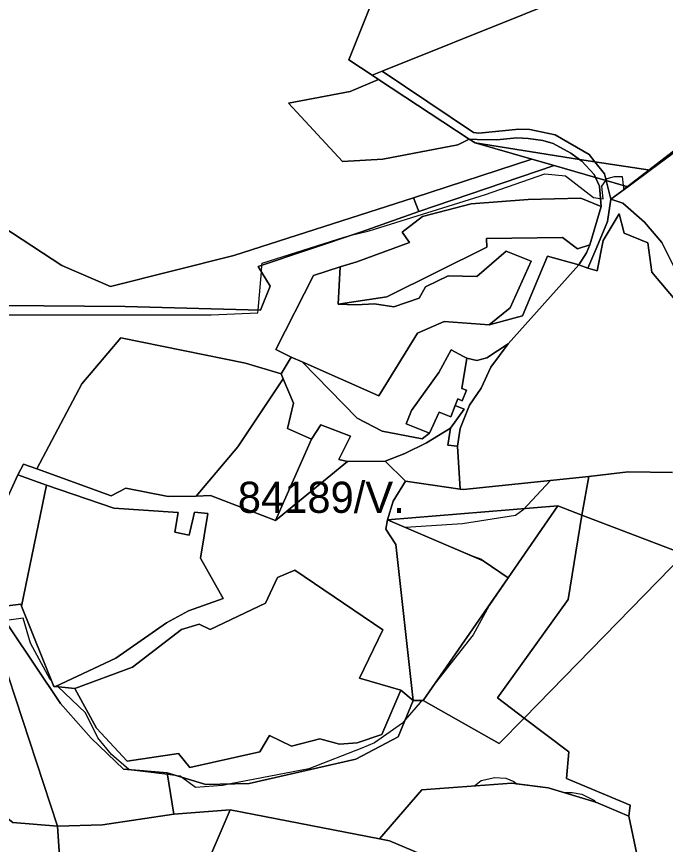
# Model space of a CAD drawing. Extents: x -477304 to -465429, y -1159113 to -1149210.
# Drawn here: x -475844.7 to -475532.4, y -1153787.9 to -1153389.4 of the extents above; entities that cross this region are included whole.
import ezdxf

# ---------------------------------------------------------------- set-up
doc = ezdxf.new("R2010")
doc.units = 0
for name, color, linetype in [('BPEJ_s', 7, 'Continuous'), ('ostatni_s', 7, 'Continuous'), ('PUPFL_s', 7, 'Continuous'), ('trav_porost_s', 7, 'Continuous'), ('zahrada_s', 7, 'Continuous')]:
    doc.layers.add(name, color=color, linetype=linetype)

msp = doc.modelspace()

# ---------------------------------------------------------------- linework, layer by layer
at = {"layer": 'BPEJ_s'}
for points in [[(-475851.96, -1153533), (-475751, -1153533), (-475728.5, -1153532), (-475728.39, -1153530.71), (-475726.86, -1153512.29), (-475726.59, -1153509.11), (-475726.5, -1153508), (-475687, -1153495.5), (-475683.62, -1153494.65), (-475675, -1153492.5), (-475619, -1153475), (-475590.5, -1153465), (-475580.5, -1153466), (-475567, -1153476.5), (-475563.7, -1153476.91), (-475562.34, -1153477.08), (-475562.99, -1153470.93), (-475561.09, -1153468.27), (-475560.98, -1153468.11), (-475560.95, -1153468.06), (-475560.44, -1153467.35), (-475556.88, -1153466.33), (-475553.31, -1153466.33), (-475552.77, -1153470.67), (-475552.67, -1153471.46), (-475552.54, -1153472.53), (-475550.84, -1153471.23), (-475540.39, -1153463.19), (-475520, -1153447.5)], [(-475851.96, -1153533), (-475751, -1153533), (-475728.5, -1153532), (-475728.39, -1153530.71), (-475726.86, -1153512.29), (-475726.59, -1153509.11), (-475726.5, -1153508), (-475687, -1153495.5), (-475683.62, -1153494.65), (-475675, -1153492.5), (-475619, -1153475), (-475590.5, -1153465), (-475580.5, -1153466), (-475567, -1153476.5), (-475563.7, -1153476.91), (-475562.34, -1153477.08), (-475562.99, -1153470.93), (-475561.09, -1153468.27), (-475560.98, -1153468.11), (-475560.95, -1153468.06), (-475560.44, -1153467.35), (-475556.88, -1153466.33), (-475553.31, -1153466.33), (-475552.77, -1153470.67), (-475552.67, -1153471.46), (-475552.54, -1153472.53), (-475550.84, -1153471.23), (-475540.39, -1153463.19), (-475520, -1153447.5)], [(-475528.97, -1153608.89), (-475550.34, -1153608.5), (-475569.29, -1153610.8), (-475587.68, -1153612.72), (-475601, -1153627), (-475604.5, -1153629.5), (-475630, -1153633.5), (-475657.46, -1153635.27), (-475625.43, -1153649.02), (-475621, -1153650.5), (-475619.57, -1153651.67), (-475608.06, -1153659.56), (-475617.27, -1153672.83), (-475625, -1153687), (-475643.27, -1153710.28), (-475649.02, -1153718.57), (-475649.77, -1153718.57), (-475650.5, -1153719.5), (-475657.63, -1153727.89), (-475659, -1153729.5), (-475672.5, -1153739), (-475678.5, -1153741.5), (-475704, -1153751.5), (-475741.66, -1153758.76), (-475745.5, -1153759.5), (-475758.5, -1153760.5), (-475765.25, -1153755.55), (-475766, -1153755), (-475767.8, -1153754.78), (-475768.33, -1153754.71), (-475772.1, -1153754.25), (-475790.5, -1153752), (-475790.7, -1153751.82), (-475799, -1153744.5), (-475805.5, -1153736.5), (-475811.5, -1153724.5), (-475824.88, -1153711.9)], [(-475528.97, -1153608.89), (-475550.34, -1153608.5), (-475569.29, -1153610.8), (-475587.68, -1153612.72), (-475601, -1153627), (-475604.5, -1153629.5), (-475630, -1153633.5), (-475657.46, -1153635.27), (-475625.43, -1153649.02), (-475621, -1153650.5), (-475619.57, -1153651.67), (-475608.06, -1153659.56), (-475617.27, -1153672.83), (-475625, -1153687), (-475643.27, -1153710.28), (-475649.02, -1153718.57), (-475649.77, -1153718.57), (-475650.5, -1153719.5), (-475657.63, -1153727.89), (-475659, -1153729.5), (-475672.5, -1153739), (-475678.5, -1153741.5), (-475704, -1153751.5), (-475741.66, -1153758.76), (-475745.5, -1153759.5), (-475758.5, -1153760.5), (-475765.25, -1153755.55), (-475766, -1153755), (-475767.8, -1153754.78), (-475768.33, -1153754.71), (-475772.1, -1153754.25), (-475790.5, -1153752), (-475790.7, -1153751.82)], [(-475790.7, -1153751.82), (-475799, -1153744.5), (-475805.5, -1153736.5), (-475811.5, -1153724.5), (-475824.88, -1153711.9), (-475825.99, -1153711.78), (-475826.72, -1153711.78), (-475827.76, -1153709.2), (-475828.5, -1153708.5), (-475838, -1153691), (-475841.5, -1153679), (-475849.5, -1153680)], [(-475824.88, -1153711.9), (-475825.99, -1153711.78), (-475826.72, -1153711.78), (-475827.76, -1153709.2), (-475828.5, -1153708.5), (-475838, -1153691), (-475841.5, -1153679), (-475849.5, -1153680)], [(-475756.99, -1153806.33), (-475741.9, -1153771.2), (-475670.03, -1153785.19), (-475649.72, -1153761.59), (-475624.25, -1153759.73), (-475621.1, -1153757.1), (-475614.5, -1153755.6), (-475609.2, -1153756), (-475605.3, -1153757.5), (-475604.03, -1153758.71), (-475588.9, -1153760.6), (-475581.23, -1153762.93), (-475577.3, -1153762.9), (-475572.6, -1153763.7), (-475566.5, -1153766.7), (-475566.24, -1153767.48), (-475565.95, -1153767.57), (-475550.09, -1153774.28), (-475542.44, -1153810.09)], [(-475624.25, -1153759.73), (-475621.1, -1153757.1), (-475614.5, -1153755.6), (-475609.2, -1153756), (-475605.3, -1153757.5), (-475604.03, -1153758.71), (-475588.9, -1153760.6), (-475581.23, -1153762.93), (-475577.3, -1153762.9), (-475572.6, -1153763.7), (-475566.5, -1153766.7), (-475566.24, -1153767.48), (-475565.95, -1153767.57), (-475550.09, -1153774.28), (-475542.44, -1153810.09)], [(-475756.99, -1153806.33), (-475741.9, -1153771.2), (-475670.03, -1153785.19), (-475649.72, -1153761.59), (-475624.25, -1153759.73)]]:
    msp.add_lwpolyline(points, dxfattribs=at)
at = {"layer": 'ostatni_s'}
for points in [[(-475668.69, -1153415.63), (-475624.85, -1153445.17), (-475622.17, -1153445.5), (-475602.95, -1153443.6), (-475597.74, -1153443.76), (-475585.5, -1153446.34), (-475569.09, -1153455.81), (-475566.37, -1153459.27), (-475573.81, -1153458.15), (-475577.89, -1153455.17), (-475586.46, -1153450.46), (-475591.43, -1153449.06), (-475598.48, -1153448), (-475603.99, -1153447.8), (-475613.57, -1153448.64), (-475622.99, -1153448.58), (-475626.84, -1153448.33), (-475670.42, -1153419.59), (-475673.48, -1153417.57)], [(-475572.58, -1153459.04), (-475573.81, -1153458.15), (-475566.37, -1153459.27), (-475561.78, -1153465.12), (-475560.87, -1153468.33), (-475566.07, -1153466.83), (-475566.74, -1153465.34)], [(-475569.79, -1153510.4), (-475574.16, -1153508.94), (-475570.35, -1153503.17), (-475568.84, -1153499.25), (-475563.38, -1153480.81), (-475564.19, -1153471), (-475566.07, -1153466.83), (-475560.87, -1153468.33), (-475558.66, -1153477.28), (-475560.35, -1153488.09), (-475565.42, -1153500.31)], [(-475574.73, -1153501.1), (-475581.96, -1153495.66), (-475618.59, -1153496.19), (-475618.43, -1153500.42), (-475666.5, -1153524.3), (-475689.92, -1153527.88), (-475688.9, -1153509.91), (-475680.91, -1153507.43), (-475655.59, -1153498.07), (-475659.07, -1153493.19), (-475649.4, -1153485.57), (-475625.88, -1153479.58), (-475598.55, -1153477.36), (-475573.19, -1153476.72), (-475563.38, -1153480.81), (-475568.84, -1153499.25)], [(-475628.05, -1153553.86), (-475623.13, -1153554.87), (-475618.43, -1153553.69), (-475608.08, -1153546.94), (-475616.41, -1153558.15), (-475621.09, -1153568.23), (-475626.74, -1153576.47), (-475631.2, -1153587.68), (-475632.49, -1153596.14), (-475637.19, -1153595.7), (-475635.79, -1153587.57), (-475629.29, -1153578.27), (-475633.55, -1153576.51), (-475632.34, -1153573.45), (-475630.17, -1153574.31), (-475628.17, -1153569.26), (-475630.34, -1153568.4)], [(-475641.43, -1153560.73), (-475635.51, -1153549.81), (-475629.63, -1153553), (-475628.05, -1153553.86), (-475630.34, -1153568.4), (-475628.17, -1153569.26), (-475630.17, -1153574.31), (-475632.34, -1153573.45), (-475633.55, -1153576.51), (-475635.72, -1153581.96), (-475641.34, -1153579.73), (-475645.88, -1153589.88), (-475657.19, -1153585.39), (-475654.62, -1153578.92)]]:
    msp.add_lwpolyline(points, close=True, dxfattribs=at)
at = {"layer": 'PUPFL_s'}
for points in [[(-475515.92, -1153287.9), (-475519.18, -1153298.61), (-475523.09, -1153304.39), (-475528.76, -1153312.77), (-475531.14, -1153360.32), (-475668.69, -1153415.63), (-475673.48, -1153417.57), (-475684.71, -1153410.17), (-475659.25, -1153346.36), (-475665.79, -1153319.52), (-475674.43, -1153216.71), (-475653.9, -1153209.59), (-475627.89, -1153203.74), (-475613.03, -1153201.52), (-475601.83, -1153200.23), (-475576.05, -1153197.07), (-475570.45, -1153196.51), (-475559.97, -1153201.88), (-475555.37, -1153214), (-475529.09, -1153283.3), (-475526.18, -1153282.23), (-475523.2, -1153281.06), (-475517.18, -1153278.69), (-475515.51, -1153278.03)], [(-475597.74, -1153443.76), (-475602.95, -1153443.6), (-475622.17, -1153445.5), (-475624.85, -1153445.17), (-475668.69, -1153415.63), (-475531.14, -1153360.32), (-475531.2, -1153370.12), (-475526.66, -1153384.3), (-475514.69, -1153395.34), (-475500.44, -1153434.27), (-475539.7, -1153463.29), (-475566.37, -1153459.27), (-475569.09, -1153455.81), (-475585.5, -1153446.34)], [(-475668.41, -1153458.08), (-475687.79, -1153459.15), (-475713.78, -1153431.01), (-475684.2, -1153425.47), (-475670.42, -1153419.59), (-475626.84, -1153448.33), (-475632.36, -1153451.19)], [(-475493.46, -1153459.75), (-475492.82, -1153484.93), (-475485.96, -1153525.23), (-475485.53, -1153549.13), (-475484.58, -1153602.24), (-475503.68, -1153602.19), (-475500.98, -1153601.49), (-475497.4, -1153591.91), (-475497, -1153568.53), (-475498.83, -1153560.34), (-475509.21, -1153546.37), (-475515.54, -1153541.79), (-475521.85, -1153525.95), (-475527.95, -1153510.61), (-475534.2, -1153498.06), (-475542.48, -1153488.38), (-475552.87, -1153479.13), (-475558.66, -1153477.28), (-475550.55, -1153471.31), (-475539.7, -1153463.29), (-475500.44, -1153434.27)], [(-475598.48, -1153448), (-475591.43, -1153449.06), (-475586.46, -1153450.46), (-475577.89, -1153455.17), (-475573.81, -1153458.15), (-475623.93, -1153450.13), (-475626.84, -1153448.33), (-475622.99, -1153448.58), (-475613.57, -1153448.64), (-475603.99, -1153447.8)], [(-475596.78, -1153457.97), (-475623.93, -1153450.13), (-475573.81, -1153458.15), (-475572.58, -1153459.04), (-475566.74, -1153465.34), (-475566.07, -1153466.83), (-475585.93, -1153461.1)], [(-475585.93, -1153461.1), (-475651.06, -1153483.16), (-475653.63, -1153476.63), (-475596.78, -1153457.97)], [(-475561.78, -1153465.12), (-475566.37, -1153459.27), (-475539.7, -1153463.29), (-475550.55, -1153471.31), (-475560.87, -1153468.33)], [(-475560.87, -1153468.33), (-475550.55, -1153471.31), (-475558.66, -1153477.28)], [(-475860.13, -1153579.58), (-475872.32, -1153636.78), (-475862.21, -1153666.07), (-475825.03, -1153779.08), (-475846.52, -1153777.32), (-475860.49, -1153766.45), (-475869.26, -1153745.4), (-475879, -1153647.09), (-475892.72, -1153543.15), (-475897.34, -1153514.33), (-475910.3, -1153503.15), (-475912.4, -1153498.87), (-475875.17, -1153475.08), (-475874.89, -1153478.85), (-475851.17, -1153528.5)], [(-475799.43, -1153519.25), (-475740.15, -1153504.46), (-475653.63, -1153476.63), (-475651.06, -1153483.16), (-475678.61, -1153492.97), (-475728.44, -1153509.73), (-475722.59, -1153519.2), (-475727.29, -1153530.74), (-475792.49, -1153528.95), (-475851.17, -1153528.5), (-475874.89, -1153478.85), (-475875.17, -1153475.08), (-475822.83, -1153509.17)], [(-475540.89, -1153498.35), (-475552.3, -1153493.56), (-475554.75, -1153484.27), (-475562.32, -1153497.18), (-475565.19, -1153511.69), (-475569.79, -1153510.4), (-475565.42, -1153500.31), (-475560.35, -1153488.09), (-475558.66, -1153477.28), (-475552.87, -1153479.13), (-475542.48, -1153488.38), (-475534.2, -1153498.06), (-475527.95, -1153510.61), (-475521.85, -1153525.95), (-475527.66, -1153525.75), (-475539.01, -1153512.42)], [(-475636.97, -1153514.1), (-475647.89, -1153519.53), (-475650.98, -1153524.94), (-475663.06, -1153529.12), (-475672.45, -1153527.72), (-475681.19, -1153528.16), (-475689.92, -1153527.88), (-475666.5, -1153524.3), (-475618.43, -1153500.42), (-475618.59, -1153496.19), (-475581.96, -1153495.66), (-475574.73, -1153501.1), (-475568.84, -1153499.25), (-475570.35, -1153503.17), (-475574.16, -1153508.94), (-475589.14, -1153504.68), (-475601.27, -1153533.38), (-475617.29, -1153537.75), (-475607.21, -1153529.51), (-475597.04, -1153507.15), (-475608.99, -1153502.36), (-475623.17, -1153514.55)], [(-475858.69, -1153641.76), (-475844.11, -1153609.9), (-475830.23, -1153614.94), (-475842.24, -1153673.19), (-475842.66, -1153672.16), (-475850.33, -1153673.17), (-475854.01, -1153645.2)], [(-475631.23, -1153616.85), (-475629.52, -1153617.08), (-475569.29, -1153610.8), (-475572.66, -1153629.41), (-475584.12, -1153624.95), (-475666.11, -1153631.56), (-475663.45, -1153622.65), (-475657.44, -1153613.04)], [(-475608.06, -1153659.56), (-475620.08, -1153651.32), (-475666.11, -1153631.56), (-475584.12, -1153624.95)], [(-475612.42, -1153739.33), (-475649.02, -1153718.57), (-475608.06, -1153659.56), (-475584.12, -1153624.95), (-475572.66, -1153629.41), (-475579.17, -1153669.95), (-475613.16, -1153717.34), (-475600.39, -1153727.01)], [(-475523.34, -1153648.1), (-475600.39, -1153727.01), (-475613.16, -1153717.34), (-475579.17, -1153669.95), (-475572.66, -1153629.41)], [(-475772.23, -1153753.44), (-475769.04, -1153773.27), (-475803.37, -1153778.4), (-475825.03, -1153779.08), (-475862.21, -1153666.07), (-475860.03, -1153665.68), (-475823.48, -1153720.08), (-475808.77, -1153736.65), (-475793.21, -1153751.6)], [(-475580.1, -1153756.17), (-475549.39, -1153768.9), (-475550.09, -1153774.28), (-475565.95, -1153767.57), (-475588.9, -1153760.6), (-475606.35, -1153758.42), (-475649.72, -1153761.59), (-475670.03, -1153785.19), (-475741.9, -1153771.2), (-475769.04, -1153773.27), (-475772.23, -1153753.44), (-475753.57, -1153759.08), (-475732.71, -1153758.52), (-475681.47, -1153746.89), (-475660.99, -1153736), (-475653.76, -1153718.54), (-475649.02, -1153718.57), (-475612.42, -1153739.33), (-475600.39, -1153727.01), (-475578.88, -1153743.31)]]:
    msp.add_lwpolyline(points, close=True, dxfattribs=at)
for points in [[(-475659.25, -1153346.36), (-475684.71, -1153410.17), (-475673.48, -1153417.57), (-475670.42, -1153419.59), (-475684.2, -1153425.47), (-475713.78, -1153431.01), (-475687.79, -1153459.15), (-475668.41, -1153458.08), (-475632.36, -1153451.19), (-475626.84, -1153448.33), (-475623.93, -1153450.13), (-475596.78, -1153457.97), (-475653.63, -1153476.63), (-475740.15, -1153504.46), (-475799.43, -1153519.25), (-475822.83, -1153509.17), (-475875.17, -1153475.08), (-475877.59, -1153433.1), (-475882.33, -1153398.08), (-475880.77, -1153394.71), (-475851.63, -1153345.16)], [(-475851.17, -1153528.5), (-475792.49, -1153528.95), (-475727.29, -1153530.74), (-475722.59, -1153519.2), (-475728.44, -1153509.73), (-475678.61, -1153492.97), (-475651.06, -1153483.16), (-475585.93, -1153461.1), (-475566.07, -1153466.83), (-475564.19, -1153471), (-475563.38, -1153480.81), (-475573.19, -1153476.72), (-475598.55, -1153477.36), (-475625.88, -1153479.58), (-475649.4, -1153485.57), (-475659.07, -1153493.19), (-475655.59, -1153498.07), (-475680.91, -1153507.43), (-475688.9, -1153509.91), (-475701.83, -1153513.93), (-475719.84, -1153549.68), (-475712.45, -1153553.33), (-475717.35, -1153561.4), (-475734.49, -1153556.24), (-475794.54, -1153544.05), (-475813.32, -1153566.21), (-475834.96, -1153607.13), (-475841.29, -1153604.8), (-475844.11, -1153609.9), (-475858.69, -1153641.76)], [(-476034.71, -1153609.09), (-475997.76, -1153576.14), (-475991.17, -1153546.59), (-475941.59, -1153528.51), (-475897.34, -1153514.33), (-475892.72, -1153543.15), (-475879, -1153647.09), (-475869.26, -1153745.4), (-475860.49, -1153766.45), (-475846.52, -1153777.32), (-475825.03, -1153779.08), (-475814.63, -1153935.2), (-475814.03, -1153985.87), (-475825.65, -1154044.41)], [(-475456.54, -1153880.98), (-475541.07, -1153838.67), (-475542.44, -1153810.09), (-475550.09, -1153774.28), (-475549.39, -1153768.9), (-475580.1, -1153756.17), (-475578.88, -1153743.31), (-475600.39, -1153727.01), (-475523.34, -1153648.1), (-475572.66, -1153629.41), (-475569.29, -1153610.8), (-475550.34, -1153608.5), (-475528.97, -1153608.89)], [(-475850.33, -1153673.17), (-475842.66, -1153672.16), (-475842.24, -1153673.19), (-475826.72, -1153711.78), (-475825.99, -1153711.78), (-475816.58, -1153712.84), (-475806.27, -1153731.98), (-475791.37, -1153747.72), (-475766.82, -1153744.11), (-475761.34, -1153750.78), (-475727.55, -1153743.35), (-475723.01, -1153735.4), (-475712.43, -1153740.61), (-475698.8, -1153737.11), (-475689.34, -1153739.63), (-475680.72, -1153739.01), (-475668.89, -1153734.97), (-475659.78, -1153713.64), (-475653.76, -1153718.54), (-475660.99, -1153736), (-475681.47, -1153746.89), (-475732.71, -1153758.52), (-475753.57, -1153759.08), (-475772.23, -1153753.44), (-475793.21, -1153751.6), (-475808.77, -1153736.65), (-475823.48, -1153720.08), (-475860.03, -1153665.68)], [(-475515.07, -1153961.8), (-475633.57, -1153941.86), (-475660.19, -1153939.52), (-475814.63, -1153935.2), (-475825.03, -1153779.08), (-475803.37, -1153778.4), (-475769.04, -1153773.27), (-475741.9, -1153771.2), (-475770.64, -1153838.12), (-475788.33, -1153879.31), (-475713.79, -1153836.29), (-475705.76, -1153840.29), (-475705.03, -1153845.03), (-475694.55, -1153898.89), (-475571.93, -1153934.58), (-475561.66, -1153935.99), (-475499, -1153946)]]:
    msp.add_lwpolyline(points, dxfattribs=at)
at = {"layer": 'trav_porost_s'}
msp.add_lwpolyline([(-475528.97, -1153608.89), (-475550.34, -1153608.5), (-475569.29, -1153610.8), (-475629.52, -1153617.08), (-475631.23, -1153616.85), (-475632.49, -1153596.14), (-475631.2, -1153587.68), (-475626.74, -1153576.47), (-475621.09, -1153568.23), (-475616.41, -1153558.15), (-475608.08, -1153546.94), (-475574.16, -1153508.94), (-475569.79, -1153510.4), (-475565.19, -1153511.69), (-475562.32, -1153497.18), (-475554.75, -1153484.27), (-475552.3, -1153493.56), (-475540.89, -1153498.35), (-475539.01, -1153512.42), (-475527.66, -1153525.75)], dxfattribs=at)
for points in [[(-475608.99, -1153502.36), (-475597.04, -1153507.15), (-475607.21, -1153529.51), (-475617.29, -1153537.75), (-475638.84, -1153536.12), (-475651.69, -1153541.78), (-475670.38, -1153571.99), (-475707.25, -1153555.51), (-475712.45, -1153553.33), (-475719.84, -1153549.68), (-475701.83, -1153513.93), (-475688.9, -1153509.91), (-475689.92, -1153527.88), (-475681.19, -1153528.16), (-475672.45, -1153527.72), (-475663.06, -1153529.12), (-475650.98, -1153524.94), (-475647.89, -1153519.53), (-475636.97, -1153514.1), (-475623.17, -1153514.55)], [(-475717.35, -1153561.4), (-475716.38, -1153563.69), (-475738.27, -1153596.43), (-475758.22, -1153620.22), (-475771.72, -1153620.37), (-475792.05, -1153616.34), (-475799.21, -1153620.04), (-475834.96, -1153607.13), (-475813.32, -1153566.21), (-475794.54, -1153544.05), (-475734.49, -1153556.24)], [(-475689.65, -1153602.53), (-475683.94, -1153591.38), (-475698.28, -1153585.94), (-475702.76, -1153592.78), (-475714.35, -1153587.68), (-475711.36, -1153575.52), (-475716.38, -1153563.69), (-475717.35, -1153561.4), (-475712.45, -1153553.33), (-475707.25, -1153555.51), (-475680.84, -1153582.64), (-475668.81, -1153588.94), (-475649.43, -1153592.59), (-475645.88, -1153589.88), (-475641.34, -1153579.73), (-475635.72, -1153581.96), (-475633.55, -1153576.51), (-475629.29, -1153578.27), (-475635.79, -1153587.57), (-475647.33, -1153594.57), (-475657.86, -1153599.67), (-475667.33, -1153603.37), (-475685.45, -1153603.49)], [(-475720.12, -1153631.87), (-475751.36, -1153619.88), (-475758.22, -1153620.22), (-475738.27, -1153596.43), (-475716.38, -1153563.69), (-475711.36, -1153575.52), (-475714.35, -1153587.68), (-475702.76, -1153592.78)], [(-475720.12, -1153631.87), (-475702.76, -1153592.78), (-475698.28, -1153585.94), (-475683.94, -1153591.38), (-475689.65, -1153602.53), (-475685.45, -1153603.49)], [(-475637.19, -1153595.7), (-475632.49, -1153596.14), (-475631.23, -1153616.85), (-475657.44, -1153613.04), (-475667.33, -1153603.37), (-475657.86, -1153599.67), (-475647.33, -1153594.57), (-475635.79, -1153587.57)], [(-475771.72, -1153620.37), (-475758.22, -1153620.22), (-475751.36, -1153619.88), (-475720.12, -1153631.87), (-475685.45, -1153603.49), (-475667.33, -1153603.37), (-475657.44, -1153613.04), (-475663.45, -1153622.65), (-475666.11, -1153631.56), (-475666.94, -1153636.16), (-475662.16, -1153643.5), (-475653.76, -1153718.54), (-475659.78, -1153713.64), (-475679.65, -1153707.76), (-475668.37, -1153684.59), (-475710.78, -1153655.91), (-475719.18, -1153659.33), (-475724.9, -1153671.81), (-475751.48, -1153684.4), (-475756.76, -1153681.89), (-475765.33, -1153684.36), (-475788.93, -1153702.48), (-475816.58, -1153712.84), (-475825.99, -1153711.78), (-475796.97, -1153698.24), (-475772.53, -1153681.24), (-475761.93, -1153675.38), (-475745.21, -1153669.42), (-475756.1, -1153650.12), (-475752.63, -1153628.5), (-475759.01, -1153627.94), (-475761.59, -1153638.97), (-475768.59, -1153637.57), (-475766.96, -1153628.11), (-475797.79, -1153626.06), (-475830.23, -1153614.94), (-475844.11, -1153609.9), (-475841.29, -1153604.8), (-475834.96, -1153607.13), (-475799.21, -1153620.04), (-475792.05, -1153616.34)], [(-475830.23, -1153614.94), (-475797.79, -1153626.06), (-475766.96, -1153628.11), (-475768.59, -1153637.57), (-475761.59, -1153638.97), (-475759.01, -1153627.94), (-475752.63, -1153628.5), (-475756.1, -1153650.12), (-475745.21, -1153669.42), (-475761.93, -1153675.38), (-475772.53, -1153681.24), (-475796.97, -1153698.24), (-475825.99, -1153711.78), (-475826.72, -1153711.78), (-475842.24, -1153673.19)], [(-475666.11, -1153631.56), (-475620.08, -1153651.32), (-475608.06, -1153659.56), (-475649.02, -1153718.57), (-475653.76, -1153718.54), (-475662.16, -1153643.5), (-475666.94, -1153636.16)], [(-475765.33, -1153684.36), (-475756.76, -1153681.89), (-475751.48, -1153684.4), (-475724.9, -1153671.81), (-475719.18, -1153659.33), (-475710.78, -1153655.91), (-475668.37, -1153684.59), (-475679.65, -1153707.76), (-475659.78, -1153713.64), (-475668.89, -1153734.97), (-475680.72, -1153739.01), (-475689.34, -1153739.63), (-475698.8, -1153737.11), (-475712.43, -1153740.61), (-475723.01, -1153735.4), (-475727.55, -1153743.35), (-475761.34, -1153750.78), (-475766.82, -1153744.11), (-475791.37, -1153747.72), (-475806.27, -1153731.98), (-475816.58, -1153712.84), (-475788.93, -1153702.48)], [(-475550.09, -1153774.28), (-475542.44, -1153810.09), (-475541.07, -1153838.67), (-475548.73, -1153834.98), (-475598.68, -1153811.42), (-475628.03, -1153801.86), (-475665.26, -1153786.1), (-475670.03, -1153785.19), (-475649.72, -1153761.59), (-475606.35, -1153758.42), (-475588.9, -1153760.6), (-475565.95, -1153767.57)], [(-475713.79, -1153836.29), (-475770.64, -1153838.12), (-475741.9, -1153771.2), (-475670.03, -1153785.19), (-475665.26, -1153786.1), (-475628.03, -1153801.86), (-475598.68, -1153811.42), (-475548.73, -1153834.98), (-475590.76, -1153884.35), (-475705.76, -1153840.29)]]:
    msp.add_lwpolyline(points, close=True, dxfattribs=at)
at = {"layer": 'zahrada_s'}
msp.add_lwpolyline([(-475638.84, -1153536.12), (-475617.29, -1153537.75), (-475601.27, -1153533.38), (-475589.14, -1153504.68), (-475574.16, -1153508.94), (-475608.08, -1153546.94), (-475618.43, -1153553.69), (-475623.13, -1153554.87), (-475628.05, -1153553.86), (-475629.63, -1153553), (-475635.51, -1153549.81), (-475641.43, -1153560.73), (-475654.62, -1153578.92), (-475657.19, -1153585.39), (-475645.88, -1153589.88), (-475649.43, -1153592.59), (-475668.81, -1153588.94), (-475680.84, -1153582.64), (-475707.25, -1153555.51), (-475670.38, -1153571.99), (-475651.69, -1153541.78)], close=True, dxfattribs=at)

# ---------------------------------------------------------------- texts
at = {"layer": 'BPEJ_s'}
msp.add_text('84189/V.', height=15, dxfattribs=at).set_placement((-475738.19, -1153628.26))

doc.saveas('drawing.dxf')
